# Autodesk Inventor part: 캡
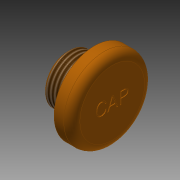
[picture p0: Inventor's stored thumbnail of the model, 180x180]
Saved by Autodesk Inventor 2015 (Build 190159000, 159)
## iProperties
Created: 2017-06
Part Number: 캡
Material: ABS 플라스틱
Document SubType Name: Modeling
Designer: mduedu
Density: 1 g/cm^3
Appearance: 주황색
Author: mduedu
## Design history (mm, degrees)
sketch "스케치1"
  geometry: L1 (0, 0)-(11, 0); L2 (11, 0)-(11, 10); L3 (11, 10)-(6.5, 10); L4 (0, 6)-(0, 0); L5 (0, 6)-(6, 6); L6 (6, 6)-(6, 9); L7 (6, 9)-(6.5, 9); L8 (6.5, 9)-(6.5, 10)
  constraints: 16 end point, 2 horizontal, 2 parallel, 2 perpendicular, 2 point on line, 1 vertical
  dimensions: "d0" = 20 diameter of L3 L1; "d2" = 12 diameter of L5 L1; "d6" = 5 distance between parallel lines of L2 L6; "d7" = 0.5 distance between parallel lines of L8 L6; "d8" = 18 diameter of L7 L1; "d9" = 6 distance between parallel lines of L6 L4
revolve "회전1" sketch "스케치1" stored, may be unused: angle "d10" = 90 deg
hole "구멍1" diameter "d22" = 8; stored, may be unused: countersink angle "d26" = 90 deg, drill point angle "d28" = 0 deg; dims "d23" = 6, "d24" = 4, "d25" = 2, "d27" = 5, "d32" = 10, "d33" = 10
chamfer "모따기1" distance "d13" = 0.5; stored, may be unused: second distance "d14" = 2, angle "d15" = 45 deg
fillet "모깎기3" dims "d29" = 1
fillet "모깎기1" dims "d16" = 0.1
fillet "모깎기2" dims "d17" = 2
sketch "스케치3"
  geometry: 2 further points
  constraints: 1 coincident, 1 other
feature "엠보싱1" sketch "스케치3" dims "d16" = 0.1, "d18" = 0.2, "d19" = 0
feature "스레드1" dims "d30" = 10, "d31" = 0
node "솔리드1"
